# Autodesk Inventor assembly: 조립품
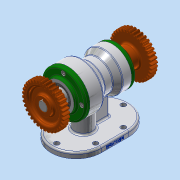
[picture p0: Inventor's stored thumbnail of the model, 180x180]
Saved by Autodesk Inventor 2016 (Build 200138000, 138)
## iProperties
Created: 2020-01
Part Number: 조립품
Document SubType Name: Assembly
Designer: woori
Author: woori
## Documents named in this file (13)
- C:\Users\woori\Desktop\700104V1002\조립품.iam
- C:\Users\woori\Desktop\700104V1002\본체.ipt
- C:\Users\woori\Desktop\700104V1002\축.ipt
- C:\Users\woori\Desktop\700104V1002\Ű 5 x 5 x 18.ipt
- C:\Users\woori\Desktop\700104V1002\베어링 6203.ipt
- C:\Users\woori\Desktop\700104V1002\베어링 6205.ipt
- C:\Users\woori\Desktop\700104V1002\앞커버.ipt
- C:\Users\woori\Desktop\700104V1002\뒤커버.ipt
- C:\Users\woori\Desktop\700104V1002\오일 실 25 38 8.ipt
- C:\Users\woori\Desktop\700104V1002\오일 실 17 30 8.ipt
- C:\Users\woori\Desktop\700104V1002\볼트 M4.ipt
- C:\Users\woori\Desktop\700104V1002\스퍼기어.ipt
- C:\Users\woori\Desktop\700104V1002\멈춤나사 M3.ipt
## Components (2 placed, 1 different names)
1. Ű 5 x 5 x 18:1 — 각도:1
2. Ű 5 x 5 x 18:2 — 각도:2
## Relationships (2: Angle 2)
- 각도:1 [Angle]: Ű 5 x 5 x 18:1
- 각도:2 [Angle]: Ű 5 x 5 x 18:2
